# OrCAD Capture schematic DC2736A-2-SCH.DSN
size Custom; title: HIGH FREQRENCY POWER SUPPLY WITH GaN TRANSISTORS; rev: 1; company: TM
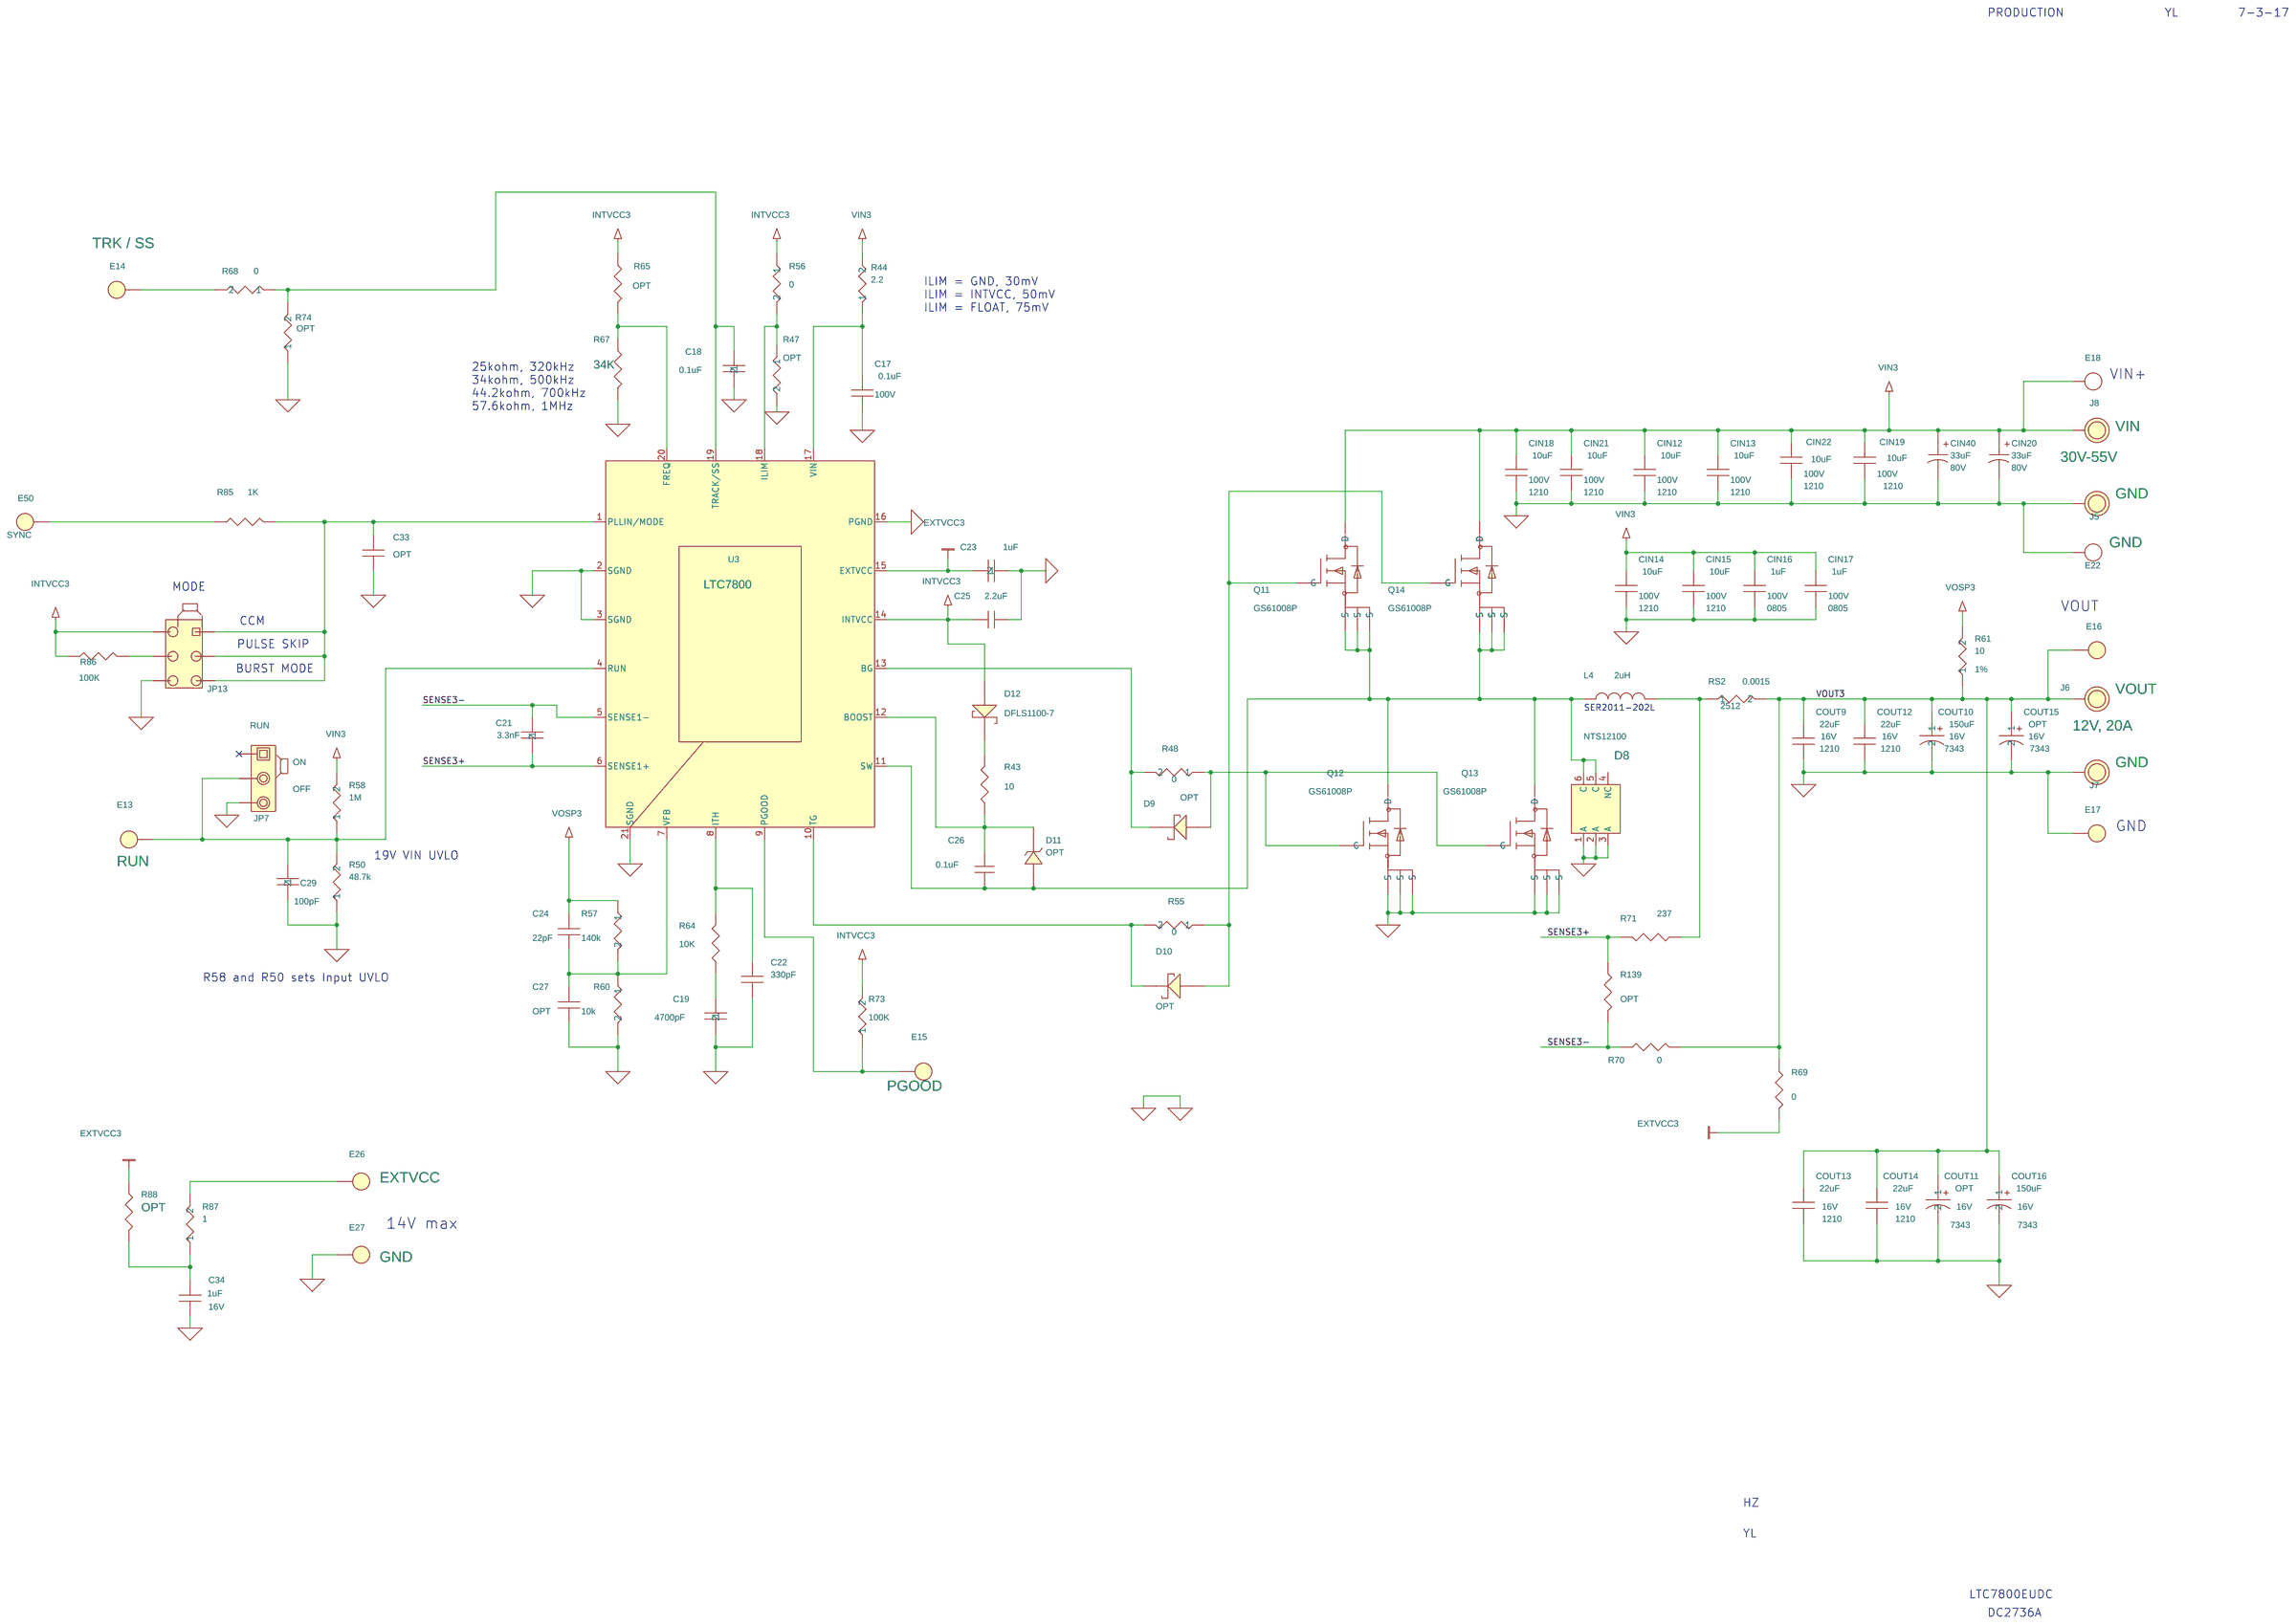
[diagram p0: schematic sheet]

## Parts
C17  0.1uF  [0603]
C18  0.1uF  [0603]
C19  4700pF  [0603]
C21  3.3nF  [0603]
C22  330pF  [0603]
C23  1uF  [0603]
C24  22pF  [0603]
C25  2.2uF  [0603]
C26  0.1uF  [0603]
C27  OPT  [0603]
C29  100pF  [0603]
C33  OPT  [0603]
C34  1uF  [0603]
CIN12  10uF  [1210]
CIN13  10uF  [1210]
CIN14  10uF  [1210]
CIN15  10uF  [1210]
CIN16  1uF  [0805]
CIN17  1uF  [0805]
CIN18  10uF  [1210]
CIN19  10uF  [1210]
CIN20  33uF  [10.3X10.3]
CIN21  10uF  [1210]
CIN22  10uF  [1210]
CIN40  33uF  [10.3X10.3]
COUT9  22uF  [1210]
COUT10  150uF  [7343]
COUT11  OPT  [7343]
COUT12  22uF  [1210]
COUT13  22uF  [1210]
COUT14  22uF  [1210]
COUT15  OPT  [7343]
COUT16  150uF  [7343]
D8  NTS12100  [SO-8FL]
D9  OPT  [SOD-323]
D10  OPT  [SOD-323]
D11  OPT  [CD0603-1005]
D12  DFLS1100-7  [SOD123-SOD323]
E13  RUN  [TP\MMX\2501-2]
E14  TRK / SS  [TP\MMX\2501-2]
E15  PGOOD  [TP\MMX\2501-2]
E16  VIN  [TP\MMX\2501-2]
E17  VIN  [TP\MMX\2501-2]
E18  GND  [TP\MMX\2501-2]
E22  GND  [TP\MMX\2501-2]
E26  EXTVCC  [TP\MMX\2501-2]
E27  GND  [TP\MMX\2501-2]
E50  SYNC  [TP\MMX\2501-2]
J5  GND  [RP325/205]
J6  GND  [RP325/205]
J7  GND  [RP325/205]
J8  GND  [RP325/205]
JP7  JMP1X3  [JUMPER3\2MM]
JP13  3 Pins 2mm Ctrs.  [JP2X3/079]
L4  2uH  [SER2900]
Q11  GS61008P  [GS61008P]
Q12  GS61008P  [GS61008P]
Q13  GS61008P  [GS61008P]
Q14  GS61008P  [GS61008P]
R43  10  [0603]
R44  2.2  [0603]
R47  OPT  [0603]
R48  0  [0603]
R50  48.7k  [0603]
R55  0  [0603]
R56  0  [0603]
R57  140k  [0603]
R58  1M  [0603]
R60  10k  [0603]
R61  10  [0603]
R64  10K  [0603]
R65  OPT  [0603]
R67  34K  [0603]
R68  0  [0603]
R69  0  [0603]
R70  0  [0603]
R71  237  [0603]
R73  100K  [0603]
R74  OPT  [0603]
R85  1K  [0603]
R86  100K  [0603]
R87  1  [0603]
R88  OPT  [0603]
R139  OPT  [0603]
RS2  0.0015  [2512]
U3  LTC7800  [UDC-20-QFN(3X4MM)]
XJP8  SHUNT  [NONE]
XJP13  2mm Ctrs.

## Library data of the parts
C17 CIN12-CIN18 CIN21 = CAP_NP_4: CAP, 1210 0.1uF 10% 200V X7R; Part Number: AVX 12102C104KAT2A; Voltage: 100V
C18 = CAP_NP_1: CAP, 0603 0.1uF 10% 25V X7R; Part Number: TDK C1608X7R1E104K
C19 = CAP_NP_1_3: CAP, 0603 4700pF 10% 50V X7R; Part Number: AVX 06035C472KAT2A
C21 = CAP_NP_1_2: CAP, 0603 1nF 10% 50V X7R; Part Number: AVX 06035C102KAT2A
C22 = CAP_NP_4: CAP, 0603 100pF 5% 50V NPO; Part Number: AVX 06035A101JAT2A
C23 = CAP_NP_1_4: CAP, 0603 1uF 20% 16V X7R; Part Number: TDK C1608X7R1C105M
C24 = CAP_NP_4: CAP, 0603 10pF 10% 50V X7R; Part Number: AVX 06035C100KAT2A
C25 = 06033C104KAT2A: CAP, 0603 2.2uF 10% 25V X7R
C26 = 06033A220JAT1A: CAP, 0603 0.1uF 10% 25V X7R; Part Number: TDK C1608X7R1E104K
C27 = 06033A102JAT2A: CAP, 0603 OPTION; Part Number: OPTION
C29 = CAP_NP_1_1: CAP, 0603 OPTION; Part Number: OPTION
C33 = CAP_NP_0: VOLTAGE: ( Opt. )
C34 = CAP_NP_3: CAP, 0603 1uF 20% 16V X7R; Voltage: 16V
CIN19 CIN22 = EMK212BJ475MG: CAP, 1210 4.7uF 10% 100V X7R; 1st Part Field: 100V; Part Number: MURATA GRM43DR72E474KW01L
CIN20 CIN40 = 4TPE220MF: CAP, 33uF 20% 80V ELEC; 1st Part Field: 80V; 5th Part Field: 50CE330LX; Part Number: PANASONIC.,  EEHZA1K330P
COUT9 COUT12-COUT14 = CAP_NP_4: CAP, 1210 22uF 10% 16V X7R; Part Number: TDK C3225X7R1C226K; Voltage: 16V
COUT10 = tant_3: CAP, 7343 150uF 20% 16V; Part Number: AVX TPSD157M016R0125; Voltage: 16V
COUT11 = tant_1: CAP, 7343 150uF 20% 16V; Part Number: AVX TPSD157M016R0125; Voltage: 16V
COUT15 = tant: CAP, 7343 150uF 20% 16V; Part Number: AVX TPSD157M016R0125; Voltage: 16V
COUT16 = tant_2: CAP, 7343 150uF 20% 16V; Part Number: PANASONIC., 16TQC150MYF; Voltage: 16V
D8 = NTS12100_1: IC, SYNCHRONOUS STEP DOWN REGULATOR; Part Number: LINEAR TECH LTC3639EMSE
D9 D10 D12 = DIODE_SCHOTTKY_1: DIODE, OPTION; Part Number: OPTION
D11 = DIODE_ZENER_0: DIODE, OPTION; Part Number: OPTION
E13-E17 E26 E27 E50 = E_0: TURRET; Part Number: MILL-MAX 2501-2-00-80-00-00-07-0
E18 = TP_KEY_1502-2_0: TURRET; 10th Part Field: 10V / 0 - 5A*; 9th Part Field: VIN; Part Number: MILL-MAX 2501-2-00-80-00-00-07-0
E22 = TP_KEY_1502-2_0: TURRET; 10th Part Field: 10V / 0 - 5A*; Part Number: MILL-MAX 2501-2-00-80-00-00-07-0
J5 J7 = TP_KEY_1502-2_2: JACK, BANANA; Part Number: KEYSTONE 575-4
J6 = TP_KEY_1502-2_2: JACK, BANANA; 10th Part Field: 12V, 20A; 9th Part Field: VOUT; Part Number: KEYSTONE 575-4
J8 = TP_KEY_1502-2_2: JACK, BANANA; 10th Part Field: 30V-55V; 9th Part Field: VIN; Part Number: KEYSTONE 575-4
JP7 = Samtec_TMM-103-02-L-S: HEADER,3PIN, 2mm; 11th Part Field: OFF; 12th Part Field: RUN; 9th Part Field: ON; Part Number: SULLINS NRPN031PAEN-RC
JP13 = Commcon2802s03g2_1: 10th Part Field: 10th??; 11th Part Field: OFF; 12th Part Field: RUN; 9th Part Field: ON
L4 = INDUCTOR: IND, 1.0uH; Part Number: VISHAY IHLP-1616BZER1R0M11
Q11-Q14 = MOS_FET_9: XSTR, N-CHANNEL DMOS FET; Part Number: INFINEON BSC520N15NS3G
R43 = CJ06-000M: RES, 0603 0 OHM JUMPER; Part Number: VISHAY CRCW06030000Z0EA
R44 = R_4: RES, 0603 2.2 OHMS 5% 1/10W; Part Number: VISHAY CRCW06032R20JNEA
R47 = R_6: RES, 0603 OPTION; Part Number: OPTION
R48 = R_8: RES, 0603 0 OHM JUMPER; Part Number: VISHAY CRCW06030000Z0EA
R50 = R_13: RES, 0603 OPTION; Part Number: OPTION
R55 = R_7: RES, 0603 0 OHM JUMPER; Part Number: VISHAY CRCW06030000Z0EA
R56 = R_1: RES, 0603 0 OHM JUMPER; Part Number: VISHAY CRCW06030000Z0EA
R57 = R_12: RES, 0603 140K OHMS 5% 1/10W; Part Number: VISHAY CRCW0603140KJNEB
R58 = R_14: RES, 0603 100K OHMS 5% 1/10W; Part Number: VISHAY CRCW0603100KJNEA
R60 = R_10: RES, 0603 10K OHMS 5% 1/10W; Part Number: VISHAY CRCW060310K0JNEA; Tol: 5%
R61 = R_11: RES, 0603 10 OHMS 1% 1/10W; Part Number: VISHAY CRCW060310R0FKEA; Tol: 1%
R64 = CR16-223JM: RES, 0603 10K OHMS 1% 1/10W; 2nd Part Field: 1%; Part Number: VISHAY CRCW060310K0FKEA
R65 = CJ06-000M: RES, 0603 OPTION; Part Number: OPTION
R67 = RES0603: RES, 0603 30.1K OHMS 1% 1/10W; 1st Part Field: 1%; 6th Part Field: ?; Part Number: VISHAY CRCW060330K1FKEA
R68 = R_5: RES, 0603 0 OHM JUMPER; Part Number: VISHAY CRCW06030000Z0EA; Tol: 1%
R69 R70 R88 = RES0603: RES, 0603 0 OHM JUMPER; 6th Part Field: ?; Part Number: VISHAY CRCW06030000Z0EA
R71 = CR16-223JM: RES, 0603 0 OHM JUMPER; 2nd Part Field: 1%; Part Number: VISHAY CRCW06030000Z0EA
R73 = R_9: RES, 0603 100K OHMS 5% 1/10W; Part Number: VISHAY CRCW0603100KJNEA
R74 = R: RES, 0603 OPTION; Part Number: OPTION
R85 R86 = R_1: %: 0.1%
R87 = R_2: RES, 0603 10 OHMS 1% 1/10W; Part Number: VISHAY CRCW060310R0FKEA; Tol: 1%
R139 = RES0603: RES, 0603 OPT; 6th Part Field: ?; Part Number: VISHAY CRCW06030000Z0EA
RS2 = R_3: RES, 2512 0.006 OHMS 5% 1/4W; Part Number: VISHAY WSL25126L000FEA18
U3 = LTC1629_4: IC, SYNCHRONOUS BUCK CONVERTER; Part Number: LINEAR TECH. LTC3895EFE
XJP8 = Samtec_2SN-BK-G: SHUNT, 2mm; Part Number: SAMTEC 2SN-BK-G
XJP13 = CommconCCIJ2MM-138G

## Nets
GND: C17.1 C18.2 C19.2 C22.1 C23.1 C25.1 C27.1 C29.2 C33.1 C34.2 CIN12.1 CIN13.1 CIN14.1 CIN15.1 CIN16.1 CIN17.1 CIN18.1 CIN19.2 CIN20.2 CIN21.1 CIN22.2 CIN40.2 COUT9.1 COUT10.2 COUT11.2 COUT12.1 COUT13.1 COUT14.1 COUT15.2 COUT16.2 D8.1(A) D8.2(A) D8.3(A) E17.1 E22.1 E27.1 J5.1 J7.1 JP7.3 JP13.6 Q12.2(S) Q12.3(S) Q12.4(S) Q13.2(S) Q13.3(S) Q13.4(S) R47.2 R50.1 R60.2 R67.1 R74.1 U3.2(SGND) U3.3(SGND) U3.16(PGND) U3.21(SGND)
VIN3: CIN12.2 CIN13.2 CIN14.2 CIN15.2 CIN16.2 CIN17.2 CIN18.2 CIN19.1 CIN20.1 CIN21.2 CIN22.1 CIN40.1 E18.1 J8.1 Q11.5(D) Q14.5(D) R44.2 R58.2
EXTVCC3: C23.2 R69.1 R88.2 U3.15(EXTVCC)
INTVCC3: C25.2 D12.2 JP13.2 R56.1 R65.1 R73.2 R86.1 U3.14(INTVCC)
SENSE3+: C21.2 R71.1 R139.2 U3.6(SENSE1+)
SENSE3-: C21.1 R70.1 R139.1 U3.5(SENSE1-)
VOSP3: C24.1 R57.1 R61.2
VOUT3: COUT9.2 COUT10.1 COUT11.1 COUT12.2 COUT13.2 COUT14.2 COUT15.1 COUT16.1 E16.1 J6.1 R61.1 R69.2 R70.2 RS2.2
N20071708: C26.2 D8.5(C) D8.6(C) D11.2(ANODE) L4.2 Q11.2(S) Q11.3(S) Q11.4(S) Q12.5(D) Q13.5(D) Q14.2(S) Q14.3(S) Q14.4(S) U3.11(SW)
N20072137: D9.2 Q12.1(G) Q13.1(G) R48.1
N20072149: D9.1 R48.2 U3.13(BG)
N20072155: D10.2 Q11.1(G) Q14.1(G) R55.1
N20072159: D10.1 R55.2 U3.10(TG)
N20072259: E15.1 R73.1 U3.9(PGOOD)
N20072575: L4.1 R71.2 RS2.1
N20072890: C18.1 R68.1 R74.2 U3.19(TRACK/SS)
N20072904: R65.2 R67.2 U3.20(FREQ)
N20072918: C29.1 E13.1 JP7.2 R50.2 R58.1 U3.4(RUN)
N20072932: C17.2 R44.1 U3.17(VIN)
N20073095: E14.1 R68.2
N20130920: C26.1 D11.1(CATHODE) R43.2 U3.12(BOOST)
N20131070: D12.1 R43.1
N20132141: C22.2 R64.2 U3.8(ITH)
N20132144: C19.1 R64.1
N20134665: C24.2 C27.2 R57.2 R60.1 U3.7(VFB)
N20136354: R47.1 R56.2 U3.18(ILIM)
N20145218: E50.1 R85.1
N20145220: C33.2 JP13.1 JP13.3 JP13.5 R85.2 U3.1(PLLIN/MODE)
N20145233: JP13.4 R86.2
N20145682: E26.1 R87.2
N20145699: C34.1 R87.1 R88.1

Not connected (* = marked no-connect by the designer): D8 4(NC); JP7 1*

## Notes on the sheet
- PRODUCTION
- YL
- 7-3-17
- ILIM = GND, 30mV
  ILIM = INTVCC, 50mV
  ILIM = FLOAT, 75mV
- 25kohm, 320kHz
  34kohm, 500kHz
  44.2kohm, 700kHz
  57.6kohm, 1MHz
- VIN+
- MODE
- VOUT
- CCM
- PULSE SKIP
- BURST MODE
- SER2011-202L
- GND
- 19V VIN UVLO
- R58 and R50 sets Input UVLO
- 14V max
- HZ
- YL
- LTC7800EUDC
- DC2736A
